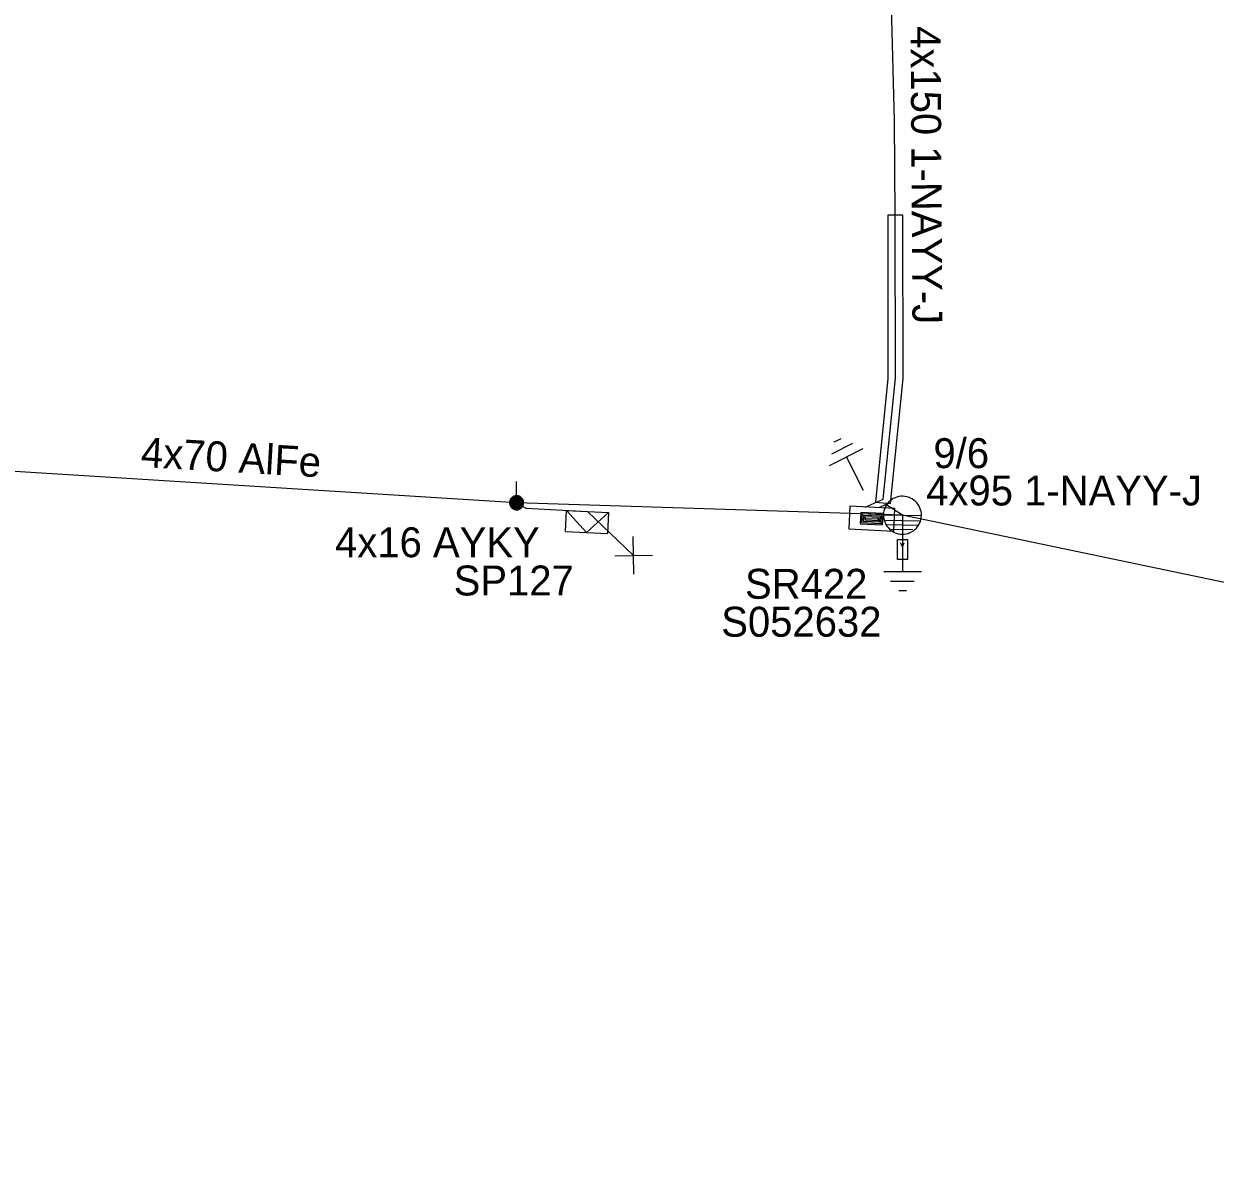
# Model space of a CAD drawing. Extents: x -762504 to -761250, y -1152974 to -1152253.
# Drawn here: x -761487.02 to -761447.44, y -1152551.93 to -1152514.18 of the extents above; entities that cross this region are included whole.
import ezdxf

# ---------------------------------------------------------------- set-up
doc = ezdxf.new("R2010")
doc.units = 0
for name, color, linetype in [('Vrstva 1', 7, 'Continuous'), ('Vrstva 12', 7, 'Continuous'), ('Vrstva 13', 7, 'Continuous'), ('Vrstva 15', 7, 'Continuous'), ('Vrstva 16', 7, 'Continuous'), ('Vrstva 2', 7, 'Continuous'), ('Vrstva 20', 7, 'Continuous'), ('Vrstva 28', 7, 'Continuous'), ('Vrstva 29', 7, 'Continuous'), ('Vrstva 30', 7, 'Continuous'), ('Vrstva 31', 7, 'Continuous'), ('Vrstva 33', 7, 'Continuous'), ('Vrstva 34', 7, 'Continuous'), ('Vrstva 5', 7, 'Continuous'), ('Vrstva 52', 7, 'Continuous'), ('Vrstva 54', 7, 'Continuous'), ('Vrstva 59', 7, 'Continuous'), ('Vrstva 6', 7, 'Continuous')]:
    doc.layers.add(name, color=color, linetype=linetype)

msp = doc.modelspace()

# ---------------------------------------------------------------- linework, layer by layer
at = {"layer": 'Vrstva 1'}
for points in [[(-761457.83, -1152530.5), (-761470.65, -1152530.09), (-761495.14, -1152528.56)], [(-761359.26, -1152551.93), (-761388.43, -1152542.63), (-761419.76, -1152537.7), (-761438.71, -1152534.5), (-761457.83, -1152530.5)]]:
    msp.add_lwpolyline(points, dxfattribs=at)
at = {"layer": 'Vrstva 13'}
for points in [[(-761470.65, -1152529.856), (-761470.65, -1152529.386)], [(-761470.415, -1152530.091), (-761470.416, -1152530.067), (-761470.42, -1152530.042), (-761470.426, -1152530.019), (-761470.435, -1152529.996), (-761470.446, -1152529.974), (-761470.459, -1152529.953), (-761470.475, -1152529.934), (-761470.492, -1152529.917), (-761470.511, -1152529.901), (-761470.532, -1152529.888), (-761470.554, -1152529.877), (-761470.577, -1152529.868), (-761470.601, -1152529.861), (-761470.625, -1152529.858), (-761470.65, -1152529.856), (-761470.674, -1152529.858), (-761470.698, -1152529.861), (-761470.722, -1152529.868), (-761470.745, -1152529.877), (-761470.767, -1152529.888), (-761470.788, -1152529.901), (-761470.807, -1152529.917), (-761470.824, -1152529.934), (-761470.84, -1152529.953), (-761470.853, -1152529.974), (-761470.864, -1152529.996), (-761470.873, -1152530.019), (-761470.879, -1152530.042), (-761470.883, -1152530.067), (-761470.885, -1152530.091), (-761470.883, -1152530.116), (-761470.879, -1152530.14), (-761470.873, -1152530.164), (-761470.864, -1152530.187), (-761470.853, -1152530.209), (-761470.84, -1152530.229), (-761470.824, -1152530.248), (-761470.807, -1152530.266), (-761470.788, -1152530.281), (-761470.767, -1152530.295), (-761470.745, -1152530.306), (-761470.722, -1152530.315), (-761470.698, -1152530.321), (-761470.674, -1152530.325), (-761470.65, -1152530.326), (-761470.625, -1152530.325), (-761470.601, -1152530.321), (-761470.577, -1152530.315), (-761470.554, -1152530.306), (-761470.532, -1152530.295), (-761470.511, -1152530.281), (-761470.492, -1152530.266), (-761470.475, -1152530.248), (-761470.459, -1152530.229), (-761470.446, -1152530.209), (-761470.435, -1152530.187), (-761470.426, -1152530.164), (-761470.42, -1152530.14), (-761470.416, -1152530.116), (-761470.415, -1152530.091)], [(-761470.415, -1152530.091), (-761470.416, -1152530.067), (-761470.42, -1152530.042), (-761470.426, -1152530.019), (-761470.435, -1152529.996), (-761470.446, -1152529.974), (-761470.459, -1152529.953), (-761470.475, -1152529.934), (-761470.492, -1152529.917), (-761470.511, -1152529.901), (-761470.532, -1152529.888), (-761470.554, -1152529.877), (-761470.577, -1152529.868), (-761470.601, -1152529.861), (-761470.625, -1152529.858), (-761470.65, -1152529.856), (-761470.674, -1152529.858), (-761470.698, -1152529.861), (-761470.722, -1152529.868), (-761470.745, -1152529.877), (-761470.767, -1152529.888), (-761470.788, -1152529.901), (-761470.807, -1152529.917), (-761470.824, -1152529.934), (-761470.84, -1152529.953), (-761470.853, -1152529.974), (-761470.864, -1152529.996), (-761470.873, -1152530.019), (-761470.879, -1152530.042), (-761470.883, -1152530.067), (-761470.885, -1152530.091), (-761470.883, -1152530.116), (-761470.879, -1152530.14), (-761470.873, -1152530.164), (-761470.864, -1152530.187), (-761470.853, -1152530.209), (-761470.84, -1152530.229), (-761470.824, -1152530.248), (-761470.807, -1152530.266), (-761470.788, -1152530.281), (-761470.767, -1152530.295), (-761470.745, -1152530.306), (-761470.722, -1152530.315), (-761470.698, -1152530.321), (-761470.674, -1152530.325), (-761470.65, -1152530.326), (-761470.625, -1152530.325), (-761470.601, -1152530.321), (-761470.577, -1152530.315), (-761470.554, -1152530.306), (-761470.532, -1152530.295), (-761470.511, -1152530.281), (-761470.492, -1152530.266), (-761470.475, -1152530.248), (-761470.459, -1152530.229), (-761470.446, -1152530.209), (-761470.435, -1152530.187), (-761470.426, -1152530.164), (-761470.42, -1152530.14), (-761470.416, -1152530.116), (-761470.415, -1152530.091)], [(-761470.444, -1152530.091), (-761470.445, -1152530.07), (-761470.449, -1152530.049), (-761470.454, -1152530.028), (-761470.462, -1152530.008), (-761470.472, -1152529.989), (-761470.483, -1152529.97), (-761470.497, -1152529.954), (-761470.512, -1152529.939), (-761470.529, -1152529.925), (-761470.547, -1152529.913), (-761470.566, -1152529.904), (-761470.586, -1152529.896), (-761470.607, -1152529.89), (-761470.628, -1152529.887), (-761470.65, -1152529.886), (-761470.671, -1152529.887), (-761470.692, -1152529.89), (-761470.713, -1152529.896), (-761470.733, -1152529.904), (-761470.752, -1152529.913), (-761470.77, -1152529.925), (-761470.787, -1152529.939), (-761470.802, -1152529.954), (-761470.816, -1152529.97), (-761470.827, -1152529.989), (-761470.837, -1152530.008), (-761470.845, -1152530.028), (-761470.85, -1152530.049), (-761470.854, -1152530.07), (-761470.855, -1152530.091), (-761470.854, -1152530.113), (-761470.85, -1152530.134), (-761470.845, -1152530.155), (-761470.837, -1152530.175), (-761470.827, -1152530.194), (-761470.816, -1152530.212), (-761470.802, -1152530.229), (-761470.787, -1152530.244), (-761470.77, -1152530.257), (-761470.752, -1152530.269), (-761470.733, -1152530.279), (-761470.713, -1152530.287), (-761470.692, -1152530.292), (-761470.671, -1152530.295), (-761470.65, -1152530.297), (-761470.628, -1152530.295), (-761470.607, -1152530.292), (-761470.586, -1152530.287), (-761470.566, -1152530.279), (-761470.547, -1152530.269), (-761470.529, -1152530.257), (-761470.512, -1152530.244), (-761470.497, -1152530.229), (-761470.483, -1152530.212), (-761470.472, -1152530.194), (-761470.462, -1152530.175), (-761470.454, -1152530.155), (-761470.449, -1152530.134), (-761470.445, -1152530.113), (-761470.444, -1152530.091)], [(-761470.474, -1152530.091), (-761470.475, -1152530.073), (-761470.478, -1152530.055), (-761470.482, -1152530.037), (-761470.489, -1152530.02), (-761470.497, -1152530.003), (-761470.507, -1152529.988), (-761470.519, -1152529.974), (-761470.532, -1152529.961), (-761470.546, -1152529.949), (-761470.562, -1152529.939), (-761470.578, -1152529.931), (-761470.595, -1152529.924), (-761470.613, -1152529.919), (-761470.631, -1152529.916), (-761470.65, -1152529.915), (-761470.668, -1152529.916), (-761470.686, -1152529.919), (-761470.704, -1152529.924), (-761470.721, -1152529.931), (-761470.737, -1152529.939), (-761470.753, -1152529.949), (-761470.767, -1152529.961), (-761470.78, -1152529.974), (-761470.792, -1152529.988), (-761470.802, -1152530.003), (-761470.81, -1152530.02), (-761470.817, -1152530.037), (-761470.822, -1152530.055), (-761470.824, -1152530.073), (-761470.825, -1152530.091), (-761470.824, -1152530.11), (-761470.822, -1152530.128), (-761470.817, -1152530.146), (-761470.81, -1152530.163), (-761470.802, -1152530.179), (-761470.792, -1152530.195), (-761470.78, -1152530.209), (-761470.767, -1152530.222), (-761470.753, -1152530.233), (-761470.737, -1152530.243), (-761470.721, -1152530.252), (-761470.704, -1152530.258), (-761470.686, -1152530.263), (-761470.668, -1152530.266), (-761470.65, -1152530.267), (-761470.631, -1152530.266), (-761470.613, -1152530.263), (-761470.595, -1152530.258), (-761470.578, -1152530.252), (-761470.562, -1152530.243), (-761470.546, -1152530.233), (-761470.532, -1152530.222), (-761470.519, -1152530.209), (-761470.507, -1152530.195), (-761470.497, -1152530.179), (-761470.489, -1152530.163), (-761470.482, -1152530.146), (-761470.478, -1152530.128), (-761470.475, -1152530.11), (-761470.474, -1152530.091)], [(-761470.503, -1152530.091), (-761470.504, -1152530.076), (-761470.507, -1152530.061), (-761470.511, -1152530.046), (-761470.516, -1152530.032), (-761470.523, -1152530.018), (-761470.531, -1152530.005), (-761470.541, -1152529.993), (-761470.552, -1152529.983), (-761470.564, -1152529.973), (-761470.577, -1152529.965), (-761470.59, -1152529.958), (-761470.604, -1152529.952), (-761470.619, -1152529.948), (-761470.634, -1152529.946), (-761470.65, -1152529.945), (-761470.665, -1152529.946), (-761470.68, -1152529.948), (-761470.695, -1152529.952), (-761470.709, -1152529.958), (-761470.723, -1152529.965), (-761470.736, -1152529.973), (-761470.747, -1152529.983), (-761470.758, -1152529.993), (-761470.768, -1152530.005), (-761470.776, -1152530.018), (-761470.783, -1152530.032), (-761470.789, -1152530.046), (-761470.793, -1152530.061), (-761470.795, -1152530.076), (-761470.796, -1152530.091), (-761470.795, -1152530.107), (-761470.793, -1152530.122), (-761470.789, -1152530.136), (-761470.783, -1152530.151), (-761470.776, -1152530.164), (-761470.768, -1152530.177), (-761470.758, -1152530.189), (-761470.747, -1152530.2), (-761470.736, -1152530.209), (-761470.723, -1152530.218), (-761470.709, -1152530.225), (-761470.695, -1152530.23), (-761470.68, -1152530.234), (-761470.665, -1152530.237), (-761470.65, -1152530.237), (-761470.634, -1152530.237), (-761470.619, -1152530.234), (-761470.604, -1152530.23), (-761470.59, -1152530.225), (-761470.577, -1152530.218), (-761470.564, -1152530.209), (-761470.552, -1152530.2), (-761470.541, -1152530.189), (-761470.531, -1152530.177), (-761470.523, -1152530.164), (-761470.516, -1152530.151), (-761470.511, -1152530.136), (-761470.507, -1152530.122), (-761470.504, -1152530.107), (-761470.503, -1152530.091)], [(-761470.533, -1152530.091), (-761470.534, -1152530.079), (-761470.536, -1152530.067), (-761470.539, -1152530.055), (-761470.543, -1152530.044), (-761470.549, -1152530.033), (-761470.555, -1152530.023), (-761470.563, -1152530.013), (-761470.572, -1152530.005), (-761470.581, -1152529.997), (-761470.591, -1152529.99), (-761470.602, -1152529.985), (-761470.614, -1152529.98), (-761470.625, -1152529.977), (-761470.637, -1152529.975), (-761470.65, -1152529.975), (-761470.662, -1152529.975), (-761470.674, -1152529.977), (-761470.686, -1152529.98), (-761470.697, -1152529.985), (-761470.708, -1152529.99), (-761470.718, -1152529.997), (-761470.728, -1152530.005), (-761470.736, -1152530.013), (-761470.744, -1152530.023), (-761470.751, -1152530.033), (-761470.756, -1152530.044), (-761470.76, -1152530.055), (-761470.764, -1152530.067), (-761470.766, -1152530.079), (-761470.766, -1152530.091), (-761470.766, -1152530.103), (-761470.764, -1152530.115), (-761470.76, -1152530.127), (-761470.756, -1152530.139), (-761470.751, -1152530.149), (-761470.744, -1152530.16), (-761470.736, -1152530.169), (-761470.728, -1152530.178), (-761470.718, -1152530.186), (-761470.708, -1152530.192), (-761470.697, -1152530.198), (-761470.686, -1152530.202), (-761470.674, -1152530.205), (-761470.662, -1152530.207), (-761470.65, -1152530.208), (-761470.637, -1152530.207), (-761470.625, -1152530.205), (-761470.614, -1152530.202), (-761470.602, -1152530.198), (-761470.591, -1152530.192), (-761470.581, -1152530.186), (-761470.572, -1152530.178), (-761470.563, -1152530.169), (-761470.555, -1152530.16), (-761470.549, -1152530.149), (-761470.543, -1152530.139), (-761470.539, -1152530.127), (-761470.536, -1152530.115), (-761470.534, -1152530.103), (-761470.533, -1152530.091)], [(-761470.563, -1152530.091), (-761470.563, -1152530.082), (-761470.565, -1152530.073), (-761470.567, -1152530.064), (-761470.57, -1152530.056), (-761470.574, -1152530.048), (-761470.579, -1152530.04), (-761470.585, -1152530.033), (-761470.591, -1152530.027), (-761470.598, -1152530.021), (-761470.606, -1152530.016), (-761470.614, -1152530.012), (-761470.623, -1152530.009), (-761470.631, -1152530.006), (-761470.64, -1152530.005), (-761470.65, -1152530.004), (-761470.659, -1152530.005), (-761470.668, -1152530.006), (-761470.676, -1152530.009), (-761470.685, -1152530.012), (-761470.693, -1152530.016), (-761470.701, -1152530.021), (-761470.708, -1152530.027), (-761470.714, -1152530.033), (-761470.72, -1152530.04), (-761470.725, -1152530.048), (-761470.729, -1152530.056), (-761470.732, -1152530.064), (-761470.735, -1152530.073), (-761470.736, -1152530.082), (-761470.737, -1152530.091), (-761470.736, -1152530.1), (-761470.735, -1152530.109), (-761470.732, -1152530.118), (-761470.729, -1152530.127), (-761470.725, -1152530.135), (-761470.72, -1152530.142), (-761470.714, -1152530.149), (-761470.708, -1152530.156), (-761470.701, -1152530.162), (-761470.693, -1152530.167), (-761470.685, -1152530.171), (-761470.676, -1152530.174), (-761470.668, -1152530.176), (-761470.659, -1152530.178), (-761470.65, -1152530.178), (-761470.64, -1152530.178), (-761470.631, -1152530.176), (-761470.623, -1152530.174), (-761470.614, -1152530.171), (-761470.606, -1152530.167), (-761470.598, -1152530.162), (-761470.591, -1152530.156), (-761470.585, -1152530.149), (-761470.579, -1152530.142), (-761470.574, -1152530.135), (-761470.57, -1152530.127), (-761470.567, -1152530.118), (-761470.565, -1152530.109), (-761470.563, -1152530.1), (-761470.563, -1152530.091)], [(-761470.592, -1152530.091), (-761470.593, -1152530.085), (-761470.594, -1152530.079), (-761470.595, -1152530.074), (-761470.597, -1152530.068), (-761470.6, -1152530.063), (-761470.603, -1152530.058), (-761470.607, -1152530.053), (-761470.611, -1152530.049), (-761470.616, -1152530.045), (-761470.621, -1152530.042), (-761470.626, -1152530.039), (-761470.632, -1152530.037), (-761470.638, -1152530.035), (-761470.644, -1152530.034), (-761470.65, -1152530.034), (-761470.656, -1152530.034), (-761470.661, -1152530.035), (-761470.667, -1152530.037), (-761470.673, -1152530.039), (-761470.678, -1152530.042), (-761470.683, -1152530.045), (-761470.688, -1152530.049), (-761470.692, -1152530.053), (-761470.696, -1152530.058), (-761470.699, -1152530.063), (-761470.702, -1152530.068), (-761470.704, -1152530.074), (-761470.706, -1152530.079), (-761470.707, -1152530.085), (-761470.707, -1152530.091), (-761470.707, -1152530.097), (-761470.706, -1152530.103), (-761470.704, -1152530.109), (-761470.702, -1152530.115), (-761470.699, -1152530.12), (-761470.696, -1152530.125), (-761470.692, -1152530.13), (-761470.688, -1152530.134), (-761470.683, -1152530.138), (-761470.678, -1152530.141), (-761470.673, -1152530.144), (-761470.667, -1152530.146), (-761470.661, -1152530.147), (-761470.656, -1152530.148), (-761470.65, -1152530.149), (-761470.644, -1152530.148), (-761470.638, -1152530.147), (-761470.632, -1152530.146), (-761470.626, -1152530.144), (-761470.621, -1152530.141), (-761470.616, -1152530.138), (-761470.611, -1152530.134), (-761470.607, -1152530.13), (-761470.603, -1152530.125), (-761470.6, -1152530.12), (-761470.597, -1152530.115), (-761470.595, -1152530.109), (-761470.594, -1152530.103), (-761470.593, -1152530.097), (-761470.592, -1152530.091)], [(-761470.622, -1152530.091), (-761470.622, -1152530.088), (-761470.622, -1152530.085), (-761470.623, -1152530.083), (-761470.624, -1152530.08), (-761470.626, -1152530.077), (-761470.627, -1152530.075), (-761470.629, -1152530.073), (-761470.631, -1152530.071), (-761470.633, -1152530.069), (-761470.636, -1152530.067), (-761470.638, -1152530.066), (-761470.641, -1152530.065), (-761470.644, -1152530.064), (-761470.647, -1152530.064), (-761470.65, -1152530.063), (-761470.652, -1152530.064), (-761470.655, -1152530.064), (-761470.658, -1152530.065), (-761470.661, -1152530.066), (-761470.663, -1152530.067), (-761470.666, -1152530.069), (-761470.668, -1152530.071), (-761470.67, -1152530.073), (-761470.672, -1152530.075), (-761470.674, -1152530.077), (-761470.675, -1152530.08), (-761470.676, -1152530.083), (-761470.677, -1152530.085), (-761470.677, -1152530.088), (-761470.677, -1152530.091), (-761470.677, -1152530.094), (-761470.677, -1152530.097), (-761470.676, -1152530.1), (-761470.675, -1152530.102), (-761470.674, -1152530.105), (-761470.672, -1152530.108), (-761470.67, -1152530.11), (-761470.668, -1152530.112), (-761470.666, -1152530.114), (-761470.663, -1152530.115), (-761470.661, -1152530.117), (-761470.658, -1152530.118), (-761470.655, -1152530.118), (-761470.652, -1152530.119), (-761470.65, -1152530.119), (-761470.647, -1152530.119), (-761470.644, -1152530.118), (-761470.641, -1152530.118), (-761470.638, -1152530.117), (-761470.636, -1152530.115), (-761470.633, -1152530.114), (-761470.631, -1152530.112), (-761470.629, -1152530.11), (-761470.627, -1152530.108), (-761470.626, -1152530.105), (-761470.624, -1152530.102), (-761470.623, -1152530.1), (-761470.622, -1152530.097), (-761470.622, -1152530.094), (-761470.622, -1152530.091)], [(-761457.199, -1152530.515), (-761457.201, -1152530.449), (-761457.211, -1152530.384), (-761457.227, -1152530.32), (-761457.249, -1152530.258), (-761457.278, -1152530.199), (-761457.313, -1152530.143), (-761457.353, -1152530.091), (-761457.399, -1152530.044), (-761457.45, -1152530.001), (-761457.504, -1152529.964), (-761457.563, -1152529.933), (-761457.624, -1152529.909), (-761457.687, -1152529.89), (-761457.752, -1152529.879), (-761457.818, -1152529.874), (-761457.884, -1152529.877), (-761457.949, -1152529.886), (-761458.013, -1152529.902), (-761458.075, -1152529.924), (-761458.134, -1152529.953), (-761458.19, -1152529.988), (-761458.242, -1152530.029), (-761458.29, -1152530.075), (-761458.332, -1152530.125), (-761458.369, -1152530.18), (-761458.4, -1152530.238), (-761458.424, -1152530.299), (-761458.443, -1152530.363), (-761458.454, -1152530.427), (-761458.459, -1152530.493), (-761458.456, -1152530.559), (-761458.447, -1152530.624), (-761458.431, -1152530.688), (-761458.409, -1152530.751), (-761458.38, -1152530.81), (-761458.345, -1152530.865), (-761458.304, -1152530.917), (-761458.258, -1152530.965), (-761458.208, -1152531.007), (-761458.153, -1152531.044), (-761458.095, -1152531.075), (-761458.034, -1152531.1), (-761457.971, -1152531.118), (-761457.905, -1152531.13), (-761457.84, -1152531.134), (-761457.774, -1152531.132), (-761457.709, -1152531.123), (-761457.645, -1152531.107), (-761457.583, -1152531.084), (-761457.524, -1152531.055), (-761457.467, -1152531.02), (-761457.415, -1152530.98), (-761457.368, -1152530.934), (-761457.326, -1152530.883), (-761457.289, -1152530.829), (-761457.258, -1152530.771), (-761457.233, -1152530.709), (-761457.215, -1152530.646), (-761457.204, -1152530.581), (-761457.199, -1152530.515)], [(-761458.46, -1152530.489), (-761457.201, -1152530.511)], [(-761458.434, -1152530.667), (-761457.263, -1152530.687)], [(-761458.348, -1152530.816), (-761457.334, -1152530.834)], [(-761458.213, -1152530.966), (-761457.485, -1152530.979)]]:
    msp.add_lwpolyline(points, dxfattribs=at)
at = {"layer": 'Vrstva 15'}
for points in [[(-761460.094, -1152528.071), (-761459.975, -1152528.011)], [(-761459.975, -1152528.011), (-761459.861, -1152527.953)], [(-761460.248, -1152528.852), (-761459.135, -1152528.284)], [(-761460.174, -1152528.466), (-761459.473, -1152528.108)], [(-761459.124, -1152529.682), (-761459.692, -1152528.568)], [(-761457.825, -1152531.14), (-761457.825, -1152532.39)], [(-761457.2, -1152532.39), (-761458.45, -1152532.39)], [(-761457.441, -1152532.701), (-761458.229, -1152532.701)], [(-761457.825, -1152533.015), (-761457.953, -1152533.015)], [(-761457.692, -1152533.015), (-761457.825, -1152533.015)]]:
    msp.add_lwpolyline(points, dxfattribs=at)
at = {"layer": 'Vrstva 16'}
for points in [[(-761457.832, -1152530.496), (-761457.832, -1152531.55)], [(-761457.995, -1152531.313), (-761457.665, -1152531.313)], [(-761457.995, -1152531.973), (-761457.995, -1152531.313)], [(-761457.832, -1152531.55), (-761457.891, -1152531.427)], [(-761457.832, -1152531.55), (-761457.773, -1152531.427)], [(-761457.665, -1152531.313), (-761457.665, -1152531.973)], [(-761457.665, -1152531.973), (-761457.995, -1152531.973)], [(-761457.832, -1152531.973), (-761457.832, -1152532.371)]]:
    msp.add_lwpolyline(points, dxfattribs=at)
at = {"layer": 'Vrstva 20'}
msp.add_lwpolyline([(-761458.32, -1152520.54), (-761458.31, -1152525.96), (-761458.73, -1152530.07), (-761458.23, -1152530.12), (-761457.81, -1152525.96), (-761457.82, -1152520.54)], close=True, dxfattribs=at)
at = {"layer": 'Vrstva 28'}
for points in [[(-761459.576, -1152530.207), (-761459.616, -1152530.956)], [(-761458.078, -1152530.286), (-761459.576, -1152530.207)], [(-761459.214, -1152530.409), (-761459.234, -1152530.787)], [(-761458.471, -1152530.448), (-761459.214, -1152530.409)], [(-761459.17, -1152530.459), (-761459.185, -1152530.742)], [(-761458.521, -1152530.493), (-761459.17, -1152530.459)], [(-761458.491, -1152530.826), (-761458.471, -1152530.448)], [(-761458.118, -1152531.035), (-761458.078, -1152530.286)], [(-761459.234, -1152530.787), (-761458.491, -1152530.826)], [(-761459.185, -1152530.742), (-761458.536, -1152530.776)], [(-761459.125, -1152530.509), (-761459.135, -1152530.697)], [(-761459.135, -1152530.697), (-761458.58, -1152530.726)], [(-761458.571, -1152530.538), (-761459.125, -1152530.509)], [(-761459.08, -1152530.558), (-761459.085, -1152530.653)], [(-761459.085, -1152530.653), (-761458.625, -1152530.677)], [(-761458.62, -1152530.582), (-761459.08, -1152530.558)], [(-761459.041, -1152530.608), (-761458.664, -1152530.627)], [(-761458.625, -1152530.677), (-761458.62, -1152530.582)], [(-761458.58, -1152530.726), (-761458.571, -1152530.538)], [(-761458.536, -1152530.776), (-761458.521, -1152530.493)], [(-761459.616, -1152530.956), (-761458.118, -1152531.035)]]:
    msp.add_lwpolyline(points, dxfattribs=at)
at = {"layer": 'Vrstva 31'}
for points in [[(-761469.029, -1152531.043), (-761468.992, -1152530.344), (-761467.594, -1152530.417), (-761467.631, -1152531.116)], [(-761468.33, -1152531.079), (-761468.992, -1152530.344)], [(-761468.33, -1152531.079), (-761467.594, -1152530.417)], [(-761469.029, -1152531.043), (-761467.631, -1152531.116)]]:
    msp.add_lwpolyline(points, dxfattribs=at)
at = {"layer": 'Vrstva 34'}
for points in [[(-761466.749, -1152532.465), (-761466.771, -1152531.215)], [(-761467.385, -1152531.851), (-761466.135, -1152531.829)]]:
    msp.add_lwpolyline(points, dxfattribs=at)
at = {"layer": 'Vrstva 5'}
for points in [[(-761459.07, -1152530.24), (-761458.47, -1152529.97), (-761458.06, -1152525.95), (-761458.07, -1152520.54), (-761458.09, -1152517.4), (-761458.27, -1152510.61), (-761458.42, -1152509.21), (-761458.57, -1152509.21)], [(-761457.83, -1152530.5), (-761458.38, -1152530.15), (-761458.61, -1152530.26)]]:
    msp.add_lwpolyline(points, dxfattribs=at)
at = {"layer": 'Vrstva 52'}
msp.add_lwpolyline([(-761470.65, -1152530.09), (-761470.34, -1152530.27), (-761468.29, -1152530.38)], dxfattribs=at)
at = {"layer": 'Vrstva 59'}
msp.add_lwpolyline([(-761468.29, -1152530.38), (-761466.76, -1152531.84)], dxfattribs=at)

# ---------------------------------------------------------------- texts
at = {"layer": 'Vrstva 12'}
msp.add_text('9/6', height=0.9943, dxfattribs=at).set_placement((-761456.8, -1152528.94))
at = {"layer": 'Vrstva 2'}
msp.add_text('4x70 AlFe', height=0.9943, rotation=356.6971, dxfattribs=at).set_placement((-761483.15, -1152528.9))
at = {"layer": 'Vrstva 29'}
msp.add_text('S052632', height=0.9943, dxfattribs=at).set_placement((-761463.85, -1152534.54))
at = {"layer": 'Vrstva 30'}
msp.add_text('SR422', height=0.9943, dxfattribs=at).set_placement((-761463.06, -1152533.28))
at = {"layer": 'Vrstva 33'}
msp.add_text('SP127', height=0.9943, dxfattribs=at).set_placement((-761472.74, -1152533.17))
at = {"layer": 'Vrstva 54'}
msp.add_text('4x16 AYKY', height=0.9943, dxfattribs=at).set_placement((-761476.68, -1152531.9))
at = {"layer": 'Vrstva 6'}
msp.add_text('4x150 1-NAYY-J', height=0.99428, rotation=270.3649, dxfattribs=at).set_placement((-761457.56, -1152514.26))
msp.add_text('4x95 1-NAYY-J', height=0.99429, dxfattribs=at).set_placement((-761457.04, -1152530.18))

doc.saveas('drawing.dxf')
